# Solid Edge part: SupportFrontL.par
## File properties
Author: Wojciech Szerszeń
Template: ISO Metric Part.par
Last saved by: wojci
Revision: 6
Application: Solid Edge
Username: Wojciech Szerszeń
Accuracy: 0.990
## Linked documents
SupportFront.par
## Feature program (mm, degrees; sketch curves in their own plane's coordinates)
part copy "CopiedPart_1"
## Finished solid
Body 1: solid body, 52 faces, 132 edges, 79 vertices.
  Faces by surface: plane 39, cylinder 12, blend 1
  Edges by curve: line 96, circle 15, ellipse 12, intersection 9
Bounding box of the edges (mm; curved faces can reach further): 37.000 x 20.000 x 66.250, from (-6, -20, -6) to (31, 0, 60.25).
Cylindrical faces by radius (mm): R1.2295 x3, R1.5 x1, R3.25 x3, R3.5 x1, R8 x1, R12 x2, R20 x1
Planar faces by outward normal: +x 4, +y 5, +z 4, -x 4, -y 4, -z 4, oblique 14
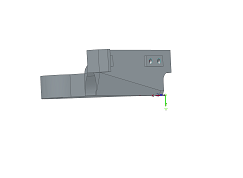
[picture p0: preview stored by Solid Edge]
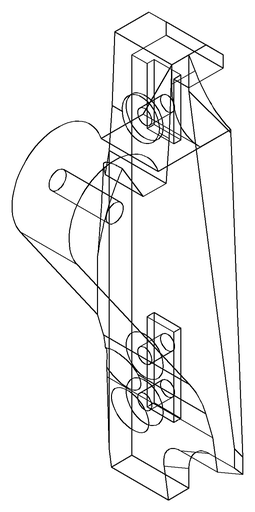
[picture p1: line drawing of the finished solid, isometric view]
